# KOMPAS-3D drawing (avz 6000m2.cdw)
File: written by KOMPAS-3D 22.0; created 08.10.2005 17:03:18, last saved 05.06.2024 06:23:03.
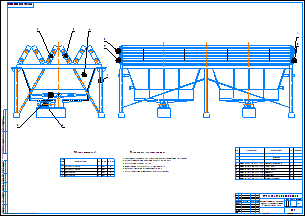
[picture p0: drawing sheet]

Sheet 1: A1, landscape

Document properties: Полное имя файла: I:\Учёба\Курсовое проектирование\Курсовой проект 4 курс\Дроб ГО 200\Диплом Дроб\АВО\avz 6000m2.cdw

Title block, sheet 1: Наименование: Аппарат воздушного охлаждения / зигзагообразный двойной / Чертеж общего вида; designation: УТЭК.18.02.09.ДП.00.00.000.ВО; scale: 1:20; Количество листов документа: 1; organisation: ПНГ; Форматы листов документа: A1; stored path: C:\Documents and Settings\Администратор\Мои документы\Курсовой проект\Чертеж.cdw

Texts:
  Normal
  Поз.
  Кол.
  УТЭК 18.02.09 ДП.00.00.001
  УТЭК 18.02.09 ДП.00.00.002
  УТЭК 18.02.09 ДП.00.00.003
  Металлоконструкция
  Секция левая
  Секция правая
  Детали
  УТЭК 18.02.09 ДП.00.00.004
  Диффузор
  УТЭК 18.02.09 ДП.00.00.005
  Вентилятор
  УТЭК 18.02.09 ДП.00.00.006
  Электродвигатель
  Техническая характеристика
  Аппарат предназначен для охлаждения газопродуктовой смеси бензина
  Производительность аппарата по сырью 34,88 кг/с
  Поверхность секции 6000 м2
  Температура среды на входе в аппарат 170␣С
  Symbol
  Давление в трубном пространстве 4 МПа
  Среда в аппарате нетоксичная, слабокоррозионная
  Таблица штуцеров
  Обоз-
  наче-
  ние
  Dу, мм
  Pу, МПа
  Ввод паров смеси
  Вывод смеси
Dimensions and other numbers on the sheet: 1; 2; 3; 6; 4; 5; 250; 1:20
